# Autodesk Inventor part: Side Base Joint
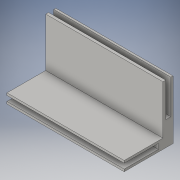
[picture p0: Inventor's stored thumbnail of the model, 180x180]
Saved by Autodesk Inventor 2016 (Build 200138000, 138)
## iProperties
Created: 2015-10
Part Number: Side Base Joint
Material: Generic
Document SubType Name: Modeling
Designer: ChombaW
Density: 1 g/cm^3
Appearance: Default
Author: ChombaW
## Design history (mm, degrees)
sketch "Sketch1"
  geometry: L1 (30.48, 2.54)-(-30.48, 2.54); L2 (-30.48, 2.54)-(-30.48, -2.54); L3 (-30.48, -2.54)-(30.48, -2.54); L4 (30.48, -2.54)-(30.48, 2.54); L5 (30.48, 2.54)-(-30.48, -2.54); L6 (-30.48, 2.54)-(30.48, -2.54); 1 further point
  constraints: 12 end point, 2 midpoint, 2 parallel, 1 horizontal, 1 perpendicular
  dimensions: "d0" = 60.96 distance of L3.end L2.end; "d1" = 5.08 distance of L2.end L1.end
extrude "Extrusion1" new body sketch "Sketch1" distance "d2" = 25.4; taper "d3" = 0 deg
sketch "Sketch2"
  geometry: L1 (101.6, 1.333)-(-101.6, 1.333); L2 (-101.6, 1.333)-(-101.6, -1.333); L3 (-101.6, -1.333)-(101.6, -1.333); L4 (101.6, -1.333)-(101.6, 1.333); L5 (101.6, 1.333)-(-101.6, -1.333); L6 (-101.6, 1.333)-(101.6, -1.333); 1 further point
  constraints: 12 end point, 2 midpoint, 2 parallel, 1 horizontal, 1 perpendicular
  dimensions: "d4" = 203.2 distance of L3.end L2.end; "d5" = 2.667 distance of L2.end L1.end
extrude "Extrusion2" cut sketch "Sketch2" distance "d6" = 17.78; taper "d7" = 0 deg
sketch "Sketch3"
  geometry: L1 (0, 0)-(0, -25.4) reference; L2 (60.96, 0)-(0, 0); L3 (0, 0)-(0, -5.249); L4 (0, -5.249)-(60.96, -5.249); L5 (60.96, -5.249)-(60.96, 0); 1 further point
  constraints: 8 end point, 2 parallel, 1 horizontal, 1 perpendicular, 1 point on line
extrude "Extrusion3" join sketch "Sketch3" distance "d8" = 25.4; taper "d9" = 0 deg
sketch "Sketch4"
  geometry: L1 (203.2, -3.792)-(0, -3.792); L2 (0, -3.792)-(0, -1.125); L3 (0, -1.125)-(203.2, -1.125); L4 (203.2, -1.125)-(203.2, -3.792); L5 (203.2, -3.792)-(0, -1.125); L6 (0, -3.792)-(203.2, -1.125); 2 further points
  constraints: 12 end point, 2 midpoint, 2 parallel, 1 horizontal, 1 perpendicular
  dimensions: "d10" = 203.2 distance of L2.end L3.end; "d11" = 2.667 distance of L1.end L2.end
extrude "Extrusion4" cut sketch "Sketch4" distance "d12" = 17.78; taper "d13" = 0 deg
body "Solid1"
